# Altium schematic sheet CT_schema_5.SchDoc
size 339 x 183 mm
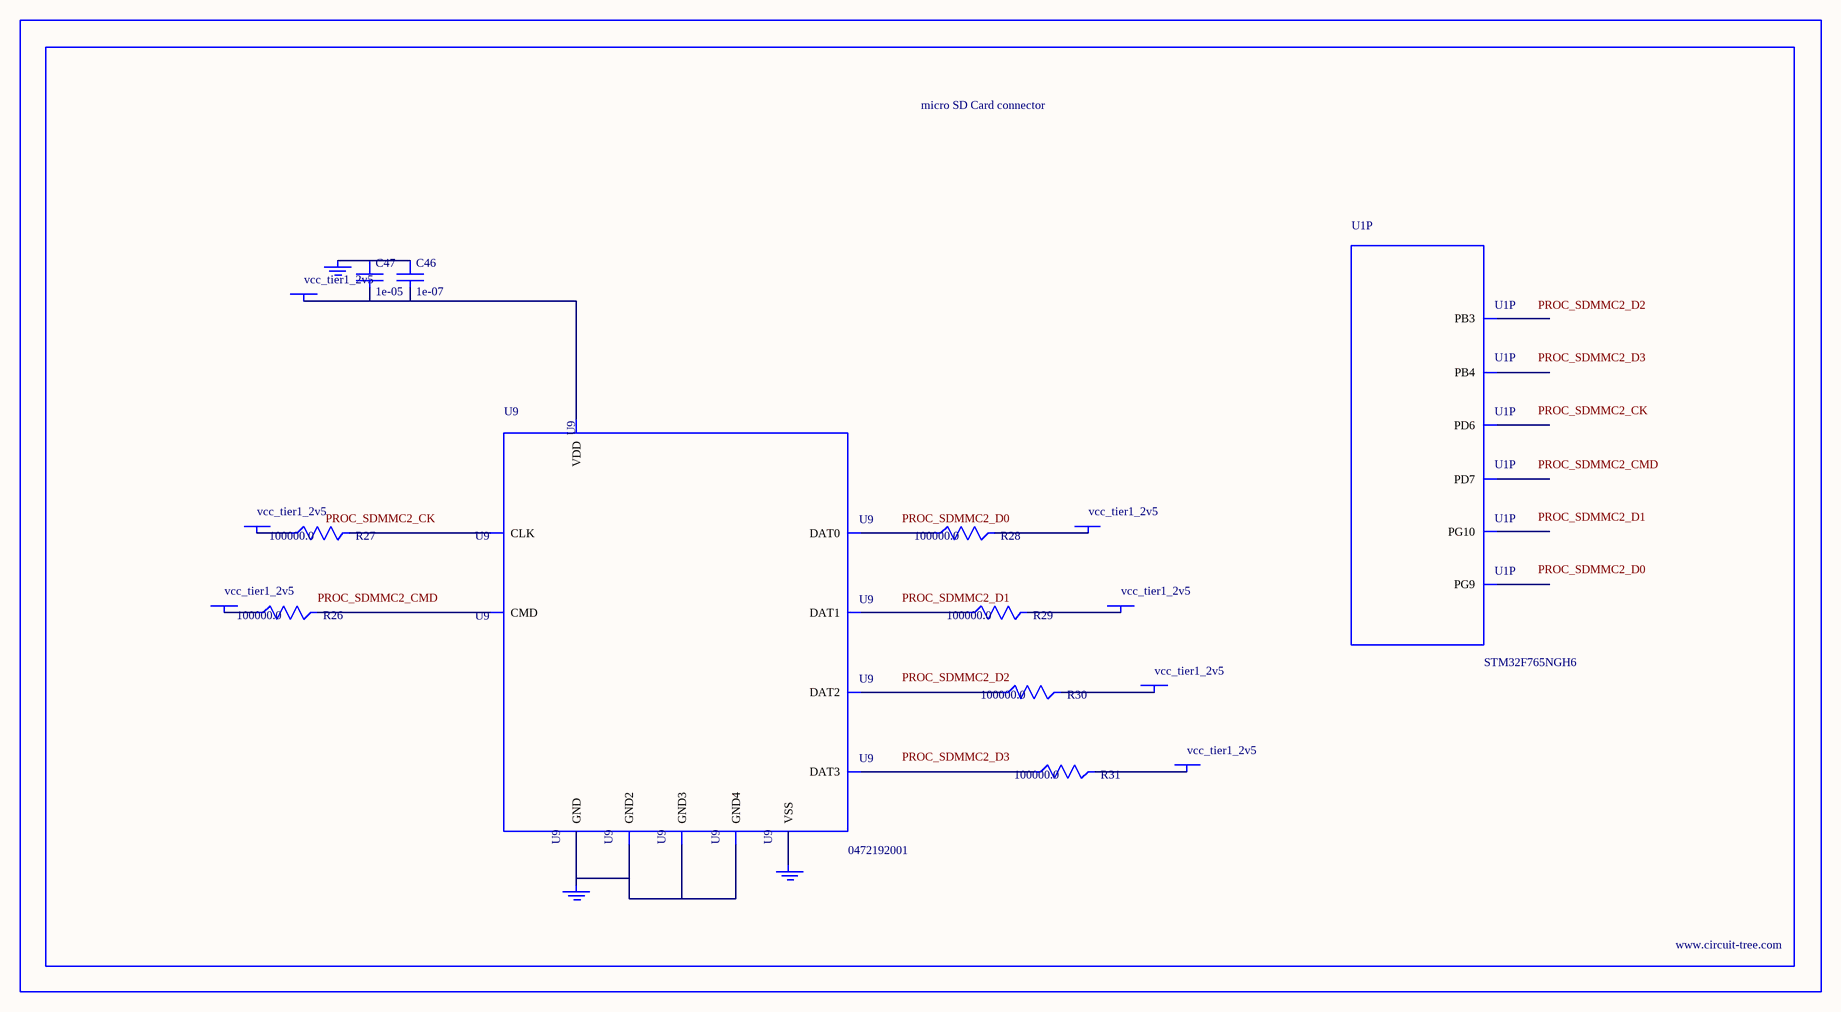
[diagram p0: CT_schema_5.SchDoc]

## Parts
BORDER4  (no value)
C46  1e-07  [C0402]
C47  1e-05  [C0805]
GND_INSTANCE_4_0  (no value)
GND_INSTANCE_4_1  (no value)
GND_INSTANCE_4_2  (no value)
POWER_INSTANCE_4_0  vcc_tier1_2v5
POWER_INSTANCE_4_1  vcc_tier1_2v5
POWER_INSTANCE_4_2  vcc_tier1_2v5
POWER_INSTANCE_4_3  vcc_tier1_2v5
POWER_INSTANCE_4_4  vcc_tier1_2v5
POWER_INSTANCE_4_5  vcc_tier1_2v5
POWER_INSTANCE_4_6  vcc_tier1_2v5
R26  100000.0  [R0603]
R27  100000.0  [R0603]
R28  100000.0  [R0603]
R29  100000.0  [R0603]
R30  100000.0  [R0603]
R31  100000.0  [R0603]
U1  STM32F765NGH6  [TFBGA216]  (part P of 18)
U9  0472192001  [MOLEX_47219-2001]

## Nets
NetC46_1: C46.1 C47.1 GND_INSTANCE_4_0.0(GND)
NetC46_2: C46.2 C47.2 POWER_INSTANCE_4_3.0(PWR) U9.4(VDD)
NetGND_INSTANCE_4_1_0: GND_INSTANCE_4_1.0(GND) U9.6(VSS)
NetGND_INSTANCE_4_2_0: GND_INSTANCE_4_2.0(GND) U9.G1(GND) U9.G2(GND2) U9.G3(GND3) U9.G4(GND4)
NetPOWER_INSTANCE_4_0_0: POWER_INSTANCE_4_0.0(PWR) R30.2
NetPOWER_INSTANCE_4_1_0: POWER_INSTANCE_4_1.0(PWR) R31.2
NetPOWER_INSTANCE_4_2_0: POWER_INSTANCE_4_2.0(PWR) R26.1
NetPOWER_INSTANCE_4_4_0: POWER_INSTANCE_4_4.0(PWR) R27.1
NetPOWER_INSTANCE_4_5_0: POWER_INSTANCE_4_5.0(PWR) R28.2
NetPOWER_INSTANCE_4_6_0: POWER_INSTANCE_4_6.0(PWR) R29.2
NetR26_2: R26.2 U9.3(CMD)
NetR27_2: R27.2 U9.5(CLK)
NetR28_1: R28.1 U9.7(DAT0)
NetR29_1: R29.1 U9.8(DAT1)
NetR30_1: R30.1 U9.1(DAT2)
NetR31_1: R31.1 U9.2(DAT3)

Not connected (* = marked no-connect by the designer): U1 A9(PB4) A10(PB3) A11(PD7) B11(PD6) C8(PG10) D9(PG9)

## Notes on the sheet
- Labels drawn without touching a wire or pin: PROC_SDMMC2_CK, PROC_SDMMC2_CMD, PROC_SDMMC2_D0, PROC_SDMMC2_D1, PROC_SDMMC2_D2, PROC_SDMMC2_D3

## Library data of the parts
BORDER4 = BORDER_PAGE4
C46 = C0402C104K3RACTU
C47 = C0805C106K8RACTU
GND_INSTANCE_4_0-GND_INSTANCE_4_2 = GND
POWER_INSTANCE_4_0-POWER_INSTANCE_4_6 = PWR
R26-R31 = RC0603JR-07100KL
